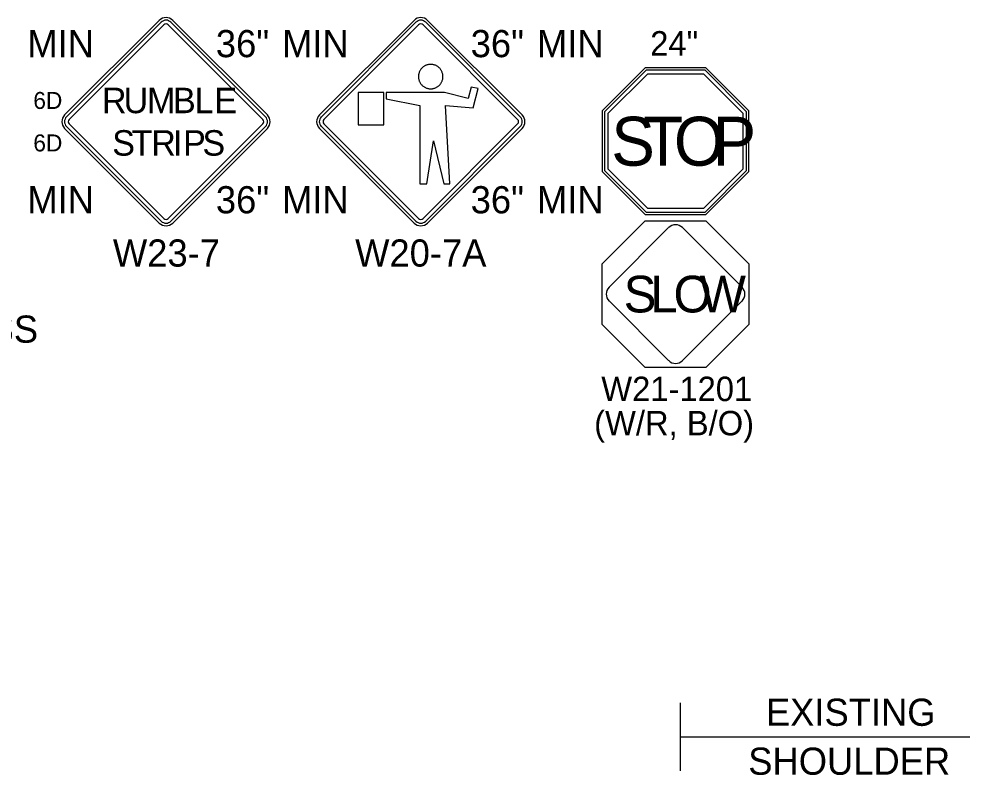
# Model space of a CAD drawing. Extents: x 99999.1 to 100095.7, y 99995 to 100010.7.
# Drawn here: x 100002.344 to 100005.12, y 100003.262 to 100005.488 of the extents above; entities that cross this region are included whole.
import ezdxf

# ---------------------------------------------------------------- set-up
doc = ezdxf.new("R2010")
doc.units = 0
doc.layers.add('TR_SN_ConstructionSigns', color=7, linetype='Continuous')
doc.layers.add('TR_WZ_WorkZoneDetails', color=7, linetype='Continuous')

msp = doc.modelspace()

# ---------------------------------------------------------------- linework, layer by layer
at = {"layer": 'TR_SN_ConstructionSigns'}
for p, q in [((100002.7568, 100005.4841), (100002.4783, 100005.2057)), ((100002.7623, 100005.4786), (100002.4839, 100005.2001)), ((100002.4916, 100005.1924), (100002.77, 100005.4708)), ((100002.7833, 100005.4708), (100003.0617, 100005.1924)), ((100003.0694, 100005.2001), (100002.791, 100005.4786)), ((100003.075, 100005.2057), (100002.7965, 100005.4841)), ((100003.5068, 100005.4841), (100003.2283, 100005.2057)), ((100003.5123, 100005.4786), (100003.2339, 100005.2001)), ((100003.2416, 100005.1924), (100003.52, 100005.4708)), ((100003.5333, 100005.4708), (100003.8117, 100005.1924)), ((100003.8194, 100005.2001), (100003.541, 100005.4786)), ((100003.825, 100005.2057), (100003.5465, 100005.4841)), ((100003.5216, 100005.3298), (100003.5211, 100005.328)), ((100003.5223, 100005.3316), (100003.5216, 100005.3298)), ((100003.523, 100005.3334), (100003.5223, 100005.3316)), ((100003.5238, 100005.3351), (100003.523, 100005.3334)), ((100003.5248, 100005.3368), (100003.5238, 100005.3351)), ((100003.5258, 100005.3385), (100003.5248, 100005.3368)), ((100003.5269, 100005.34), (100003.5258, 100005.3385)), ((100003.5281, 100005.3415), (100003.5269, 100005.34)), ((100003.5293, 100005.343), (100003.5281, 100005.3415)), ((100003.5307, 100005.3443), (100003.5293, 100005.343)), ((100003.5321, 100005.3456), (100003.5307, 100005.3443)), ((100003.5336, 100005.3468), (100003.5321, 100005.3456)), ((100003.5351, 100005.348), (100003.5336, 100005.3468)), ((100003.5367, 100005.349), (100003.5351, 100005.348)), ((100003.5384, 100005.35), (100003.5367, 100005.349)), ((100003.5401, 100005.3509), (100003.5384, 100005.35)), ((100003.5418, 100005.3517), (100003.5401, 100005.3509)), ((100003.5436, 100005.3524), (100003.5418, 100005.3517)), ((100003.5454, 100005.353), (100003.5436, 100005.3524)), ((100003.5473, 100005.3535), (100003.5454, 100005.353)), ((100003.5492, 100005.3539), (100003.5473, 100005.3535)), ((100003.5511, 100005.3542), (100003.5492, 100005.3539)), ((100003.5529, 100005.3544), (100003.5511, 100005.3542)), ((100003.5549, 100005.3545), (100003.5529, 100005.3544)), ((100003.5568, 100005.3545), (100003.5549, 100005.3545)), ((100003.5587, 100005.3544), (100003.5568, 100005.3545)), ((100003.5606, 100005.3542), (100003.5587, 100005.3544)), ((100003.5625, 100005.3539), (100003.5606, 100005.3542)), ((100003.5644, 100005.3535), (100003.5625, 100005.3539)), ((100003.5662, 100005.353), (100003.5644, 100005.3535)), ((100003.5681, 100005.3524), (100003.5662, 100005.353)), ((100003.5698, 100005.3517), (100003.5681, 100005.3524)), ((100003.5716, 100005.3509), (100003.5698, 100005.3517)), ((100003.5733, 100005.35), (100003.5716, 100005.3509)), ((100003.575, 100005.349), (100003.5733, 100005.35)), ((100003.5765, 100005.348), (100003.575, 100005.349)), ((100003.5781, 100005.3468), (100003.5765, 100005.348)), ((100003.5795, 100005.3456), (100003.5781, 100005.3468)), ((100003.581, 100005.3443), (100003.5795, 100005.3456)), ((100003.5823, 100005.343), (100003.581, 100005.3443)), ((100003.5835, 100005.3415), (100003.5823, 100005.343)), ((100003.5847, 100005.34), (100003.5835, 100005.3415)), ((100003.5858, 100005.3385), (100003.5847, 100005.34)), ((100003.5868, 100005.3368), (100003.5858, 100005.3385)), ((100003.5878, 100005.3351), (100003.5868, 100005.3368)), ((100003.5886, 100005.3334), (100003.5878, 100005.3351)), ((100003.5893, 100005.3316), (100003.5886, 100005.3334)), ((100003.59, 100005.3298), (100003.5893, 100005.3316)), ((100003.5906, 100005.328), (100003.59, 100005.3298)), ((100004.1871, 100005.3443), (100004.0606, 100005.2178)), ((100004.1899, 100005.3376), (100004.0673, 100005.215)), ((100004.366, 100005.3443), (100004.1871, 100005.3443)), ((100004.3632, 100005.3376), (100004.1899, 100005.3376)), ((100004.4858, 100005.215), (100004.3632, 100005.3376)), ((100004.4926, 100005.2178), (100004.366, 100005.3443)), ((100003.52, 100005.3223), (100003.5198, 100005.3204)), ((100003.5198, 100005.3204), (100003.5198, 100005.3185)), ((100003.5198, 100005.3185), (100003.5198, 100005.3166)), ((100003.5198, 100005.3166), (100003.52, 100005.3147)), ((100003.5203, 100005.3243), (100003.52, 100005.3223)), ((100003.52, 100005.3147), (100003.5203, 100005.3128)), ((100003.5206, 100005.3261), (100003.5203, 100005.3243)), ((100003.5203, 100005.3128), (100003.5206, 100005.3109)), ((100003.5211, 100005.328), (100003.5206, 100005.3261)), ((100003.5206, 100005.3109), (100003.5211, 100005.309)), ((100003.5211, 100005.309), (100003.5216, 100005.3072)), ((100003.5216, 100005.3072), (100003.5223, 100005.3054)), ((100003.5223, 100005.3054), (100003.523, 100005.3036)), ((100003.523, 100005.3036), (100003.5238, 100005.3019)), ((100003.5238, 100005.3019), (100003.5248, 100005.3002)), ((100003.5868, 100005.3002), (100003.5878, 100005.3019)), ((100003.5878, 100005.3019), (100003.5886, 100005.3036)), ((100003.5886, 100005.3036), (100003.5893, 100005.3054)), ((100003.5893, 100005.3054), (100003.59, 100005.3072)), ((100003.59, 100005.3072), (100003.5906, 100005.309)), ((100003.591, 100005.3261), (100003.5906, 100005.328)), ((100003.5906, 100005.309), (100003.591, 100005.3109)), ((100003.5914, 100005.3243), (100003.591, 100005.3261)), ((100003.591, 100005.3109), (100003.5914, 100005.3128)), ((100003.5917, 100005.3223), (100003.5914, 100005.3243)), ((100003.5914, 100005.3128), (100003.5917, 100005.3147)), ((100003.5918, 100005.3204), (100003.5917, 100005.3223)), ((100003.5917, 100005.3147), (100003.5918, 100005.3166)), ((100003.5918, 100005.3185), (100003.5918, 100005.3204)), ((100003.5918, 100005.3166), (100003.5918, 100005.3185)), ((100004.0786, 100005.2104), (100004.1945, 100005.3263)), ((100004.1945, 100005.3263), (100004.3586, 100005.3263)), ((100004.3586, 100005.3263), (100004.4746, 100005.2104)), ((100003.5248, 100005.3002), (100003.5258, 100005.2986)), ((100003.5258, 100005.2986), (100003.5269, 100005.297)), ((100003.5269, 100005.297), (100003.5281, 100005.2955)), ((100003.5281, 100005.2955), (100003.5293, 100005.2941)), ((100003.5293, 100005.2941), (100003.5307, 100005.2927)), ((100003.5307, 100005.2927), (100003.5321, 100005.2914)), ((100003.5321, 100005.2914), (100003.5336, 100005.2902)), ((100003.5336, 100005.2902), (100003.5351, 100005.289)), ((100003.5351, 100005.289), (100003.5367, 100005.288)), ((100003.5367, 100005.288), (100003.5384, 100005.287)), ((100003.5384, 100005.287), (100003.5401, 100005.2861)), ((100003.5401, 100005.2861), (100003.5418, 100005.2853)), ((100003.5418, 100005.2853), (100003.5436, 100005.2846)), ((100003.5436, 100005.2846), (100003.5454, 100005.284)), ((100003.5454, 100005.284), (100003.5473, 100005.2835)), ((100003.5473, 100005.2835), (100003.5492, 100005.2831)), ((100003.5492, 100005.2831), (100003.5511, 100005.2828)), ((100003.5511, 100005.2828), (100003.5529, 100005.2826)), ((100003.5529, 100005.2826), (100003.5549, 100005.2825)), ((100003.5549, 100005.2825), (100003.5568, 100005.2825)), ((100003.5568, 100005.2825), (100003.5587, 100005.2826)), ((100003.5587, 100005.2826), (100003.5606, 100005.2828)), ((100003.5606, 100005.2828), (100003.5625, 100005.2831)), ((100003.5625, 100005.2831), (100003.5644, 100005.2835)), ((100003.5644, 100005.2835), (100003.5662, 100005.284)), ((100003.5662, 100005.284), (100003.5681, 100005.2846)), ((100003.5681, 100005.2846), (100003.5698, 100005.2853)), ((100003.5698, 100005.2853), (100003.5716, 100005.2861)), ((100003.5716, 100005.2861), (100003.5733, 100005.287)), ((100003.5733, 100005.287), (100003.575, 100005.288)), ((100003.575, 100005.288), (100003.5765, 100005.289)), ((100003.5765, 100005.289), (100003.5781, 100005.2902)), ((100003.5781, 100005.2902), (100003.5795, 100005.2914)), ((100003.5795, 100005.2914), (100003.581, 100005.2927)), ((100003.581, 100005.2927), (100003.5823, 100005.2941)), ((100003.5823, 100005.2941), (100003.5835, 100005.2955)), ((100003.5835, 100005.2955), (100003.5847, 100005.297)), ((100003.5847, 100005.297), (100003.5858, 100005.2986)), ((100003.5858, 100005.2986), (100003.5868, 100005.3002)), ((100003.6753, 100005.2869), (100003.6656, 100005.2541)), ((100003.6953, 100005.2833), (100003.6753, 100005.2869)), ((100003.6803, 100005.2265), (100003.6953, 100005.2833)), ((100003.3424, 100005.2712), (100003.3424, 100005.1765)), ((100003.4177, 100005.2712), (100003.3424, 100005.2712)), ((100003.4177, 100005.1765), (100003.4177, 100005.2712)), ((100003.5961, 100005.2712), (100003.4247, 100005.2712)), ((100003.4247, 100005.2712), (100003.4247, 100005.2531)), ((100003.4247, 100005.2531), (100003.5242, 100005.2333)), ((100003.6656, 100005.2541), (100003.5961, 100005.2712)), ((100003.5242, 100005.2333), (100003.5242, 100005.003)), ((100003.6124, 100005.003), (100003.5993, 100005.2334)), ((100003.5993, 100005.2334), (100003.6803, 100005.2265)), ((100004.0606, 100005.2178), (100004.0606, 100005.0389)), ((100004.0673, 100005.215), (100004.0673, 100005.0417)), ((100004.0786, 100005.0463), (100004.0786, 100005.2104)), ((100004.4746, 100005.2104), (100004.4746, 100005.0463)), ((100004.4858, 100005.0417), (100004.4858, 100005.215)), ((100004.4926, 100005.0389), (100004.4926, 100005.2178)), ((100002.4783, 100005.1659), (100002.7568, 100004.8875)), ((100002.4839, 100005.1714), (100002.7623, 100004.893)), ((100002.77, 100004.9007), (100002.4916, 100005.1792)), ((100003.0617, 100005.1792), (100002.7833, 100004.9007)), ((100002.791, 100004.893), (100003.0694, 100005.1714)), ((100002.7965, 100004.8875), (100003.075, 100005.1659)), ((100003.2283, 100005.1659), (100003.5068, 100004.8875)), ((100003.2339, 100005.1714), (100003.5123, 100004.893)), ((100003.52, 100004.9007), (100003.2416, 100005.1792)), ((100003.3424, 100005.1765), (100003.4177, 100005.1765)), ((100003.8117, 100005.1792), (100003.5333, 100004.9007)), ((100003.541, 100004.893), (100003.8194, 100005.1714)), ((100003.5465, 100004.8875), (100003.825, 100005.1659)), ((100003.5444, 100005.003), (100003.5641, 100005.1297)), ((100003.5641, 100005.1297), (100003.5944, 100005.003)), ((100004.0606, 100005.0389), (100004.1871, 100004.9123)), ((100004.0673, 100005.0417), (100004.1899, 100004.9191)), ((100004.1945, 100004.9303), (100004.0786, 100005.0463)), ((100004.4746, 100005.0463), (100004.3586, 100004.9303)), ((100004.3632, 100004.9191), (100004.4858, 100005.0417)), ((100004.366, 100004.9123), (100004.4926, 100005.0389)), ((100003.5242, 100005.003), (100003.5444, 100005.003)), ((100003.5944, 100005.003), (100003.6124, 100005.003)), ((100004.1899, 100004.9191), (100004.3632, 100004.9191)), ((100004.3586, 100004.9303), (100004.1945, 100004.9303)), ((100004.1871, 100004.9123), (100004.366, 100004.9123)), ((100004.2562, 100004.874), (100004.0809, 100004.6987)), ((100004.4722, 100004.6987), (100004.2969, 100004.874)), ((100004.0809, 100004.658), (100004.2562, 100004.4827)), ((100004.2969, 100004.4827), (100004.4722, 100004.658))]:
    msp.add_line(p, q, dxfattribs=at)
msp.add_lwpolyline([(100004.4926, 100004.7678), (100004.4926, 100004.5889), (100004.366, 100004.4623), (100004.1871, 100004.4623), (100004.0606, 100004.5889), (100004.0606, 100004.7678), (100004.1871, 100004.8943), (100004.366, 100004.8943)], close=True, dxfattribs=at)
for centre, radius, start, end in [((100002.7767, 100005.4642), 0.0281, 45, 135), ((100002.7767, 100005.4642), 0.0203, 45, 135), ((100002.7767, 100005.4642), 0.00937, 45, 135), ((100003.5267, 100005.4642), 0.0281, 45, 135), ((100003.5267, 100005.4642), 0.0203, 45, 135), ((100003.5267, 100005.4642), 0.00937, 45, 135), ((100002.4982, 100005.1858), 0.0281, 135, 225), ((100002.4982, 100005.1858), 0.0203, 135, 225), ((100002.4982, 100005.1858), 0.00937, 135, 225), ((100003.0551, 100005.1858), 0.00937, 315, 45), ((100003.0551, 100005.1858), 0.0203, 315, 45), ((100003.0551, 100005.1858), 0.0281, 315, 45), ((100003.2482, 100005.1858), 0.0281, 135, 225), ((100003.2482, 100005.1858), 0.0203, 135, 225), ((100003.2482, 100005.1858), 0.00937, 135, 225), ((100003.8051, 100005.1858), 0.00937, 315, 45), ((100003.8051, 100005.1858), 0.0203, 315, 45), ((100003.8051, 100005.1858), 0.0281, 315, 45), ((100002.7767, 100004.9074), 0.0281, 225, 315), ((100002.7767, 100004.9074), 0.0203, 225, 315), ((100002.7767, 100004.9074), 0.00937, 225, 315), ((100003.5267, 100004.9074), 0.0281, 225, 315), ((100003.5267, 100004.9074), 0.0203, 225, 315), ((100003.5267, 100004.9074), 0.00937, 225, 315), ((100004.2766, 100004.8536), 0.0288, 45, 135), ((100004.1013, 100004.6783), 0.0288, 135, 225), ((100004.4518, 100004.6783), 0.0288, 315, 45), ((100004.2766, 100004.5031), 0.0288, 225, 315)]:
    msp.add_arc(centre, radius, start, end, dxfattribs=at)
at = {"layer": 'TR_WZ_WorkZoneDetails'}
for p, q in [((100004.2907, 100003.2755), (100004.2907, 100003.4755)), ((100004.2907, 100003.3755), (100005.2907, 100003.3755))]:
    msp.add_line(p, q, dxfattribs=at)

# ---------------------------------------------------------------- texts
at = {"layer": 'TR_SN_ConstructionSigns'}
for s, height, p in [('MIN', 0.08, (100002.3684, 100005.3756)), ('36"', 0.08, (100002.9234, 100005.3756)), ('MIN', 0.08, (100003.1184, 100005.3756)), ('36"', 0.08, (100003.6734, 100005.3756)), ('MIN', 0.08, (100003.8684, 100005.3756)), ('36"', 0.08, (100002.9234, 100004.916)), ('36"', 0.08, (100003.6734, 100004.916)), ('MIN', 0.08, (100002.3684, 100004.916)), ('MIN', 0.08, (100003.1184, 100004.916)), ('MIN', 0.08, (100003.8684, 100004.916)), ('W23-7', 0.08, (100002.6204, 100004.7592)), ('W20-7A', 0.08, (100003.3334, 100004.7592)), ('40 MPH OR LESS', 0.08, (100001.5202, 100004.5352)), ('W21-1201', 0.072, (100004.0578, 100004.3633)), ('(W/R, B/O)', 0.072, (100004.0369, 100004.2625))]:
    msp.add_text(s, height=height, rotation=360, dxfattribs=at).set_placement(p)
for s, height, p in [('24"', 0.072, (100004.2019, 100005.3803)), ('R', 0.075, (100002.588, 100005.2108)), ('U', 0.075, (100002.6518, 100005.2108)), ('M', 0.075, (100002.7208, 100005.2108)), ('B', 0.075, (100002.7973, 100005.2108)), ('L', 0.075, (100002.861, 100005.2108)), ('E', 0.075, (100002.9188, 100005.2108)), ('6D', 0.05, (100002.3861, 100005.2233)), ('S', 0.144, (100004.0872, 100005.0563)), ('T', 0.144, (100004.1808, 100005.0563)), ('O', 0.144, (100004.2715, 100005.0563)), ('P', 0.144, (100004.3853, 100005.0563)), ('6D', 0.05, (100002.3861, 100005.0983)), ('S', 0.075, (100002.6184, 100005.0858)), ('T', 0.075, (100002.6754, 100005.0858)), ('R', 0.075, (100002.7332, 100005.0858)), ('I', 0.075, (100002.7969, 100005.0858)), ('P', 0.075, (100002.8269, 100005.0858)), ('S', 0.075, (100002.8839, 100005.0858)), ('S', 0.108, (100004.1238, 100004.6243)), ('L', 0.108, (100004.2026, 100004.6243)), ('O', 0.108, (100004.2706, 100004.6243)), ('W', 0.108, (100004.3473, 100004.6243))]:
    msp.add_text(s, height=height, dxfattribs=at).set_placement(p)
at = {"layer": 'TR_WZ_WorkZoneDetails'}
for s, p in [('EXISTING', (100004.5424, 100003.4075)), ('SHOULDER', (100004.4905, 100003.2635))]:
    msp.add_text(s, height=0.08, rotation=360, dxfattribs=at).set_placement(p)

doc.saveas('drawing.dxf')
